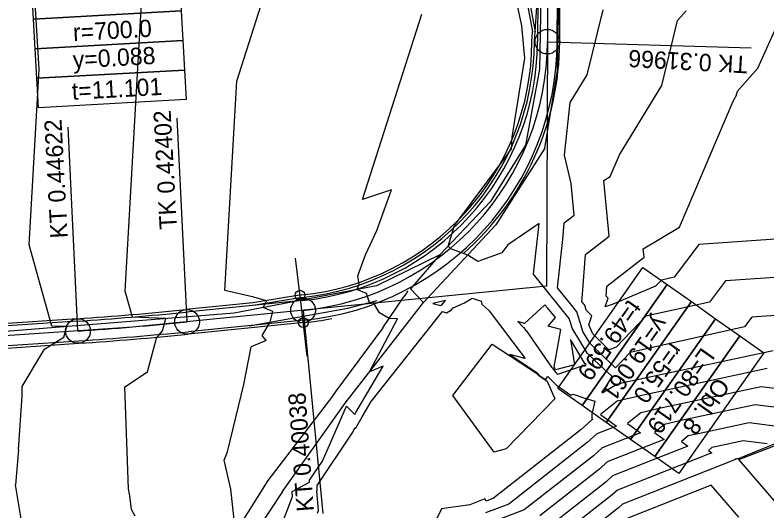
# Model space of a CAD drawing. Extents: x -549394 to -546608, y -1037055 to -1033629.
# Drawn here: x -547750.8 to -547598.3, y -1035451.6 to -1035351 of the extents above; entities that cross this region are included whole.
import ezdxf

# ---------------------------------------------------------------- set-up
doc = ezdxf.new("R2010")
doc.units = 0
for name, color, linetype in [('hlavni_vrst', 7, 'Continuous'), ('hrana_L', 7, 'Continuous'), ('norm_vrst', 7, 'Continuous'), ('POLYGONY_SITUACE_PO', 7, 'Continuous'), ('u_sirka_1_0m', 7, 'Continuous'), ('x_navrh_C1', 7, 'Continuous'), ('x_osa_C1', 7, 'Continuous'), ('x_popis_oblouky_C1', 7, 'Continuous'), ('x_popis_pricne_rezy_C1', 7, 'Continuous')]:
    doc.layers.add(name, color=color, linetype=linetype)

msp = doc.modelspace()

# ---------------------------------------------------------------- linework, layer by layer
at = {"layer": 'hlavni_vrst'}
for p, q in [((-547647.98, -1035353.14), (-547650.68, -1035340.75)), ((-547647.39, -1035359.7), (-547647.98, -1035353.14)), ((-547649.93, -1035375.76), (-547647.39, -1035359.7)), ((-547650.08, -1035378.1), (-547649.93, -1035375.76)), ((-547651.52, -1035380.05), (-547650.08, -1035378.1)), ((-547661.62, -1035393.67), (-547651.52, -1035380.05)), ((-547662.95, -1035397.82), (-547661.62, -1035393.67)), ((-547644.51, -1035393.23), (-547650.83, -1035397.56)), ((-547645.62, -1035403.52), (-547644.51, -1035393.23)), ((-547650.83, -1035397.56), (-547652.05, -1035399.2)), ((-547662.37, -1035398.39), (-547662.95, -1035397.82)), ((-547658.97, -1035399.67), (-547662.37, -1035398.39)), ((-547656.9, -1035400.98), (-547658.97, -1035399.67)), ((-547652.05, -1035399.2), (-547656.9, -1035400.98)), ((-547640.35, -1035410.1), (-547645.62, -1035403.52)), ((-547661.95, -1035410.34), (-547659.65, -1035409.33)), ((-547659.65, -1035409.33), (-547658.1, -1035408.42)), ((-547658.1, -1035408.42), (-547656.27, -1035409.01)), ((-547656.27, -1035409.01), (-547656.09, -1035409.61)), ((-547656.09, -1035409.61), (-547654.6, -1035410.95)), ((-547678.52, -1035429.33), (-547664.06, -1035411.12)), ((-547664.06, -1035411.12), (-547663.26, -1035411.34)), ((-547663.26, -1035411.34), (-547662.29, -1035410.73)), ((-547662.29, -1035410.73), (-547661.95, -1035410.34)), ((-547654.6, -1035410.95), (-547647.35, -1035420.64)), ((-547638.38, -1035412.49), (-547640.35, -1035410.1)), ((-547638.06, -1035413.56), (-547638.38, -1035412.49)), ((-547637.78, -1035414.45), (-547638.06, -1035413.56)), ((-547634.65, -1035419.6), (-547637.78, -1035414.45)), ((-547647.35, -1035420.64), (-547650.46, -1035419.84)), ((-547650.46, -1035419.84), (-547644.86, -1035423.52)), ((-547633.26, -1035420.98), (-547634.65, -1035419.6)), ((-547596.99, -1035419.04), (-547627.42, -1035425.56)), ((-547629.69, -1035424.3), (-547633.26, -1035420.98)), ((-547644.33, -1035424.14), (-547644.86, -1035423.52)), ((-547644.33, -1035424.14), (-547643.18, -1035424.92)), ((-547643.18, -1035424.92), (-547642.7, -1035424.3)), ((-547642.7, -1035424.3), (-547640.93, -1035426.07)), ((-547631.68, -1035427.63), (-547629.69, -1035424.3)), ((-547640.93, -1035426.07), (-547638.06, -1035428.05)), ((-547628.73, -1035425.87), (-547631.68, -1035427.63)), ((-547627.42, -1035425.56), (-547628.73, -1035425.87)), ((-547638.06, -1035428.05), (-547637.58, -1035427.89)), ((-547637.58, -1035427.89), (-547635.4, -1035428.6)), ((-547680.35, -1035432.43), (-547678.52, -1035429.33)), ((-547635.4, -1035428.6), (-547633.2, -1035429.31)), ((-547633.2, -1035429.31), (-547633.77, -1035431.89)), ((-547681.72, -1035434.81), (-547680.35, -1035432.43)), ((-547633.77, -1035431.89), (-547633.81, -1035432.76)), ((-547633.81, -1035433.08), (-547635.99, -1035435.06)), ((-547633.81, -1035432.76), (-547633.8, -1035432.83)), ((-547633.58, -1035432.99), (-547633.81, -1035433.08)), ((-547633.8, -1035432.83), (-547633.58, -1035432.99)), ((-547689.5, -1035446.37), (-547682.27, -1035435.59)), ((-547682.27, -1035435.59), (-547681.86, -1035434.67)), ((-547681.86, -1035434.67), (-547681.72, -1035434.81)), ((-547635.99, -1035435.06), (-547653.72, -1035448.96)), ((-547609.45, -1035438.69), (-547610.16, -1035439.26)), ((-547608.41, -1035438.45), (-547609.45, -1035438.69)), ((-547603.13, -1035437.32), (-547608.41, -1035438.45)), ((-547598.25, -1035437.97), (-547603.13, -1035437.32)), ((-547609.48, -1035439.74), (-547628.59, -1035447.31)), ((-547610.16, -1035439.26), (-547609.48, -1035439.74)), ((-547689.51, -1035447.51), (-547689.5, -1035446.37)), ((-547689.58, -1035447.55), (-547689.51, -1035447.51)), ((-547689.22, -1035451.44), (-547689.58, -1035447.55)), ((-547628.59, -1035447.31), (-547629.64, -1035448.26)), ((-547655.48, -1035449.1), (-547658.55, -1035450.34)), ((-547655.24, -1035449.54), (-547655.48, -1035449.1)), ((-547653.72, -1035448.96), (-547655.24, -1035449.54)), ((-547629.64, -1035448.26), (-547638.14, -1035454.93)), ((-547658.55, -1035450.34), (-547664.28, -1035451.11)), ((-547689.44, -1035452.02), (-547689.22, -1035451.44)), ((-547664.28, -1035451.11), (-547670.13, -1035463.03))]:
    msp.add_line(p, q, dxfattribs=at)
at = {"layer": 'hrana_L'}
for p, q in [((-547643.97, -1035335.51), (-547644.38, -1035361.94)), ((-547640.75, -1035362.22), (-547640.27, -1035335.27)), ((-547644.38, -1035361.94), (-547647.23, -1035377.35)), ((-547643.35, -1035377.93), (-547640.75, -1035362.22)), ((-547647.23, -1035377.35), (-547654.32, -1035388.75)), ((-547643.35, -1035377.93), (-547653.27, -1035393.54)), ((-547654.32, -1035388.75), (-547664.64, -1035399.6)), ((-547667.91, -1035409.29), (-547653.27, -1035393.54)), ((-547664.64, -1035399.6), (-547677.46, -1035405.86)), ((-547664.64, -1035399.6), (-547670.59, -1035406.48)), ((-547677.46, -1035405.86), (-547706.33, -1035411.42)), ((-547667.91, -1035409.29), (-547670.59, -1035406.48)), ((-547676.17, -1035414.41), (-547671.94, -1035408.13)), ((-547671.28, -1035407.14), (-547671.94, -1035408.13)), ((-547671.28, -1035407.14), (-547671.11, -1035406.86)), ((-547683.81, -1035429.72), (-547667.91, -1035409.29)), ((-547683.3, -1035410.4), (-547677.37, -1035408.87)), ((-547703.28, -1035414.02), (-547683.3, -1035410.4)), ((-547706.33, -1035411.42), (-547756.77, -1035415.5)), ((-547676.17, -1035414.41), (-547685.69, -1035427.24)), ((-547685.69, -1035427.24), (-547686.59, -1035428.55)), ((-547686.59, -1035428.55), (-547699.54, -1035445.41)), ((-547696.51, -1035447.59), (-547683.81, -1035429.72)), ((-547699.54, -1035445.41), (-547712.17, -1035465.45)), ((-547696.51, -1035447.59), (-547709.78, -1035467.43))]:
    msp.add_line(p, q, dxfattribs=at)
at = {"layer": 'norm_vrst'}
for p, q in [((-547728.43, -1035406.99), (-547724.59, -1035338.68)), ((-547705.79, -1035364.36), (-547697.76, -1035339.16)), ((-547600.1, -1035361.72), (-547589.66, -1035338.3)), ((-547745.88, -1035361.93), (-547747.23, -1035340.5)), ((-547634.71, -1035363.08), (-547631.51, -1035349.89)), ((-547616.41, -1035352.04), (-547614.65, -1035350.07)), ((-547680.29, -1035388.4), (-547668.31, -1035350.8)), ((-547619.6, -1035365.22), (-547616.41, -1035352.04)), ((-547747.89, -1035397.56), (-547745.88, -1035361.93)), ((-547604.26, -1035366.39), (-547600.1, -1035361.72)), ((-547600.1, -1035361.72), (-547600.1, -1035361.72)), ((-547600.1, -1035361.72), (-547600.1, -1035361.72)), ((-547600.1, -1035361.72), (-547600.1, -1035361.72)), ((-547600.1, -1035361.72), (-547600.1, -1035361.72)), ((-547600.1, -1035361.72), (-547600.1, -1035361.72)), ((-547638.16, -1035368.73), (-547634.71, -1035363.08)), ((-547708.21, -1035406.83), (-547705.79, -1035364.36)), ((-547628.21, -1035379.29), (-547619.6, -1035365.22)), ((-547604.5, -1035367.37), (-547604.26, -1035366.39)), ((-547616, -1035394), (-547605.14, -1035368.41)), ((-547605.14, -1035368.41), (-547604.5, -1035367.37)), ((-547639.31, -1035379.36), (-547638.16, -1035368.73)), ((-547630.09, -1035383.74), (-547628.21, -1035379.29)), ((-547638.01, -1035385.14), (-547639.31, -1035379.36)), ((-547631.37, -1035384.49), (-547630.09, -1035383.74)), ((-547637.41, -1035391.55), (-547638.01, -1035385.14)), ((-547630.31, -1035395.83), (-547631.37, -1035384.49)), ((-547674.41, -1035386.43), (-547680.29, -1035388.4)), ((-547677.41, -1035394.64), (-547674.41, -1035386.43)), ((-547639.43, -1035393.12), (-547637.41, -1035391.55)), ((-547639.68, -1035396.51), (-547639.43, -1035393.12)), ((-547623.36, -1035398.37), (-547616, -1035394)), ((-547679.71, -1035399.6), (-547677.41, -1035394.64)), ((-547635.08, -1035399.54), (-547630.31, -1035395.83)), ((-547584.5, -1035395.56), (-547612.1, -1035397.52)), ((-547743.35, -1035414.04), (-547747.89, -1035397.56)), ((-547640.73, -1035406.29), (-547639.68, -1035396.51)), ((-547612.1, -1035397.52), (-547617.09, -1035404.15)), ((-547623.2, -1035400.1), (-547623.36, -1035398.37)), ((-547681.26, -1035403.85), (-547679.71, -1035399.6)), ((-547635.68, -1035407.58), (-547635.08, -1035399.54)), ((-547630.73, -1035405.96), (-547623.2, -1035400.1)), ((-547588.83, -1035403.62), (-547606.71, -1035404.89)), ((-547681, -1035405.64), (-547681.26, -1035403.85)), ((-547619.67, -1035404.73), (-547620.87, -1035405.97)), ((-547617.09, -1035404.15), (-547619.67, -1035404.73)), ((-547606.71, -1035404.89), (-547609.94, -1035409.18)), ((-547681.45, -1035406.63), (-547681, -1035405.64)), ((-547679.47, -1035407.42), (-547681.45, -1035406.63)), ((-547637.88, -1035409.86), (-547640.73, -1035406.29)), ((-547630.88, -1035407.97), (-547630.73, -1035405.96)), ((-547620.87, -1035405.97), (-547629.7, -1035409.66)), ((-547726.98, -1035412.27), (-547728.43, -1035406.99)), ((-547702.32, -1035408.17), (-547708.21, -1035406.83)), ((-547699.81, -1035408.9), (-547702.32, -1035408.17)), ((-547678.91, -1035409.27), (-547679.47, -1035407.42)), ((-547635.84, -1035409.07), (-547635.68, -1035407.58)), ((-547630.48, -1035408.36), (-547630.88, -1035407.97)), ((-547700.44, -1035410.29), (-547699.81, -1035408.9)), ((-547678.08, -1035409.33), (-547678.91, -1035409.27)), ((-547676.83, -1035411.37), (-547678.08, -1035409.33)), ((-547663.47, -1035408.86), (-547666.04, -1035409.45)), ((-547666.04, -1035409.45), (-547664.46, -1035409.89)), ((-547664.46, -1035409.89), (-547664.28, -1035409.78)), ((-547664.28, -1035409.78), (-547663.47, -1035408.86)), ((-547643.37, -1035409.82), (-547647.45, -1035413.53)), ((-547643.3, -1035409.74), (-547643.37, -1035409.82)), ((-547642.82, -1035410.34), (-547643.3, -1035409.74)), ((-547635.4, -1035409.61), (-547635.84, -1035409.07)), ((-547635.24, -1035409.81), (-547635.4, -1035409.61)), ((-547634.94, -1035410.81), (-547635.24, -1035409.81)), ((-547631.12, -1035410.18), (-547630.48, -1035408.36)), ((-547629.7, -1035409.66), (-547631.12, -1035410.18)), ((-547609.94, -1035409.18), (-547622.83, -1035412.07)), ((-547698.48, -1035411.07), (-547700.44, -1035410.29)), ((-547699.07, -1035413.26), (-547698.48, -1035411.07)), ((-547641.19, -1035412.32), (-547642.82, -1035410.34)), ((-547636.81, -1035411.15), (-547637.88, -1035409.86)), ((-547636.15, -1035413.32), (-547636.81, -1035411.15)), ((-547633.78, -1035411.94), (-547634.94, -1035410.81)), ((-547720.2, -1035412.54), (-547726.98, -1035412.27)), ((-547720.88, -1035414.99), (-547720.2, -1035412.54)), ((-547678.86, -1035423.36), (-547673.24, -1035412.6)), ((-547674.91, -1035412.54), (-547676.83, -1035411.37)), ((-547673.24, -1035412.6), (-547674.91, -1035412.54)), ((-547642.66, -1035414.07), (-547641.19, -1035412.32)), ((-547634.43, -1035413.79), (-547633.78, -1035411.94)), ((-547622.83, -1035412.07), (-547628.84, -1035418.3)), ((-547601.32, -1035412.26), (-547602.8, -1035414.22)), ((-547593.16, -1035411.68), (-547601.32, -1035412.26)), ((-547740.29, -1035414.17), (-547743.35, -1035414.04)), ((-547740.9, -1035416.33), (-547740.29, -1035414.17)), ((-547700.67, -1035415.98), (-547699.07, -1035413.26)), ((-547647.45, -1035413.53), (-547648.81, -1035413.09)), ((-547648.81, -1035413.09), (-547647.69, -1035414.3)), ((-547647.69, -1035414.3), (-547647.62, -1035414.37)), ((-547647.62, -1035414.37), (-547647.15, -1035415)), ((-547640.08, -1035414.77), (-547642.66, -1035414.07)), ((-547635.59, -1035415.14), (-547636.15, -1035413.32)), ((-547633.62, -1035415.62), (-547634.43, -1035413.79)), ((-547602.8, -1035414.22), (-547626, -1035419.41)), ((-547722.1, -1035416.53), (-547720.88, -1035414.99)), ((-547647.15, -1035415), (-547647.11, -1035414.95)), ((-547647.11, -1035414.95), (-547641.97, -1035422.4)), ((-547641.45, -1035422.31), (-547640.08, -1035414.77)), ((-547634.11, -1035417.57), (-547635.59, -1035415.14)), ((-547630.34, -1035418.89), (-547633.62, -1035415.62)), ((-547744.84, -1035418.71), (-547740.9, -1035416.33)), ((-547723.93, -1035423.33), (-547722.1, -1035416.53)), ((-547699.86, -1035417), (-547702.88, -1035418.25)), ((-547699.86, -1035417), (-547700.67, -1035415.98)), ((-547635.19, -1035421.62), (-547638.15, -1035416.76)), ((-547638.15, -1035416.76), (-547637.29, -1035421.92)), ((-547745.43, -1035419.76), (-547744.84, -1035418.71)), ((-547704.41, -1035425.92), (-547702.88, -1035418.25)), ((-547662, -1035428.11), (-547654.04, -1035417.7)), ((-547654.04, -1035417.7), (-547644.84, -1035423.75)), ((-547631.38, -1035420.28), (-547634.11, -1035417.57)), ((-547629.72, -1035418.67), (-547630.34, -1035418.89)), ((-547628.84, -1035418.3), (-547629.72, -1035418.67)), ((-547749.31, -1035426.34), (-547745.43, -1035419.76)), ((-547628.99, -1035422.51), (-547631.38, -1035420.28)), ((-547626, -1035419.41), (-547628.99, -1035422.51)), ((-547637.29, -1035421.92), (-547641.14, -1035422.95)), ((-547640.69, -1035423.79), (-547635.33, -1035422.01)), ((-547635.33, -1035422.01), (-547635.1, -1035422.09)), ((-547635.13, -1035421.68), (-547635.19, -1035421.62)), ((-547634.96, -1035421.84), (-547635.13, -1035421.68)), ((-547635.1, -1035422.09), (-547634.96, -1035421.84)), ((-547728.53, -1035426.36), (-547723.93, -1035423.33)), ((-547681.63, -1035431.55), (-547676.1, -1035422.19)), ((-547676.1, -1035422.19), (-547678.86, -1035423.36)), ((-547641.97, -1035422.4), (-547641.87, -1035422.51)), ((-547641.87, -1035422.51), (-547641.1, -1035423.44)), ((-547641.14, -1035422.95), (-547641.45, -1035422.31)), ((-547641.1, -1035423.44), (-547640.9, -1035423.64)), ((-547598.22, -1035422.69), (-547623.62, -1035428.14)), ((-547644.6, -1035424.03), (-547644.84, -1035423.75)), ((-547644.6, -1035424.03), (-547642.88, -1035425.2)), ((-547640.9, -1035423.64), (-547640.69, -1035423.79)), ((-547749.32, -1035428.27), (-547749.31, -1035426.34)), ((-547727.79, -1035447.08), (-547728.53, -1035426.36)), ((-547707.69, -1035439.57), (-547704.41, -1035425.92)), ((-547642.88, -1035425.2), (-547641.29, -1035428.81)), ((-547599.44, -1035426.35), (-547619.82, -1035430.72)), ((-547567.08, -1035425.79), (-547604.13, -1035441.01)), ((-547603.97, -1035441.1), (-547566.27, -1035426.59)), ((-547580.62, -1035428.85), (-547599.44, -1035426.35)), ((-547653.59, -1035439.61), (-547662, -1035428.11)), ((-547750.1, -1035439.07), (-547749.32, -1035428.27)), ((-547641.29, -1035428.81), (-547651.17, -1035438.94)), ((-547628.63, -1035429.3), (-547632.01, -1035432)), ((-547623.62, -1035428.14), (-547628.63, -1035429.3)), ((-547688.45, -1035441.45), (-547683.57, -1035430.33)), ((-547683.57, -1035430.33), (-547681.88, -1035431.97)), ((-547619.82, -1035430.72), (-547623.84, -1035431.65)), ((-547600.67, -1035430.01), (-547616.01, -1035433.3)), ((-547586.5, -1035431.89), (-547600.67, -1035430.01)), ((-547681.88, -1035431.97), (-547681.63, -1035431.55)), ((-547632.01, -1035432), (-547628.76, -1035434.34)), ((-547623.84, -1035431.65), (-547626.55, -1035433.82)), ((-547626.55, -1035433.82), (-547623.94, -1035435.69)), ((-547619.04, -1035434), (-547621.08, -1035435.63)), ((-547616.01, -1035433.3), (-547619.04, -1035434)), ((-547601.9, -1035433.66), (-547612.21, -1035435.88)), ((-547592.37, -1035434.93), (-547601.9, -1035433.66)), ((-547628.76, -1035434.34), (-547632.76, -1035435.93)), ((-547623.94, -1035435.69), (-547631.72, -1035438.77)), ((-547621.08, -1035435.63), (-547619.12, -1035437.04)), ((-547632.76, -1035435.93), (-547634.72, -1035437.7)), ((-547619.12, -1035437.04), (-547630.68, -1035441.62)), ((-547614.25, -1035436.34), (-547615.62, -1035437.44)), ((-547612.21, -1035435.88), (-547614.25, -1035436.34)), ((-547634.72, -1035437.7), (-547650.6, -1035450.15)), ((-547631.72, -1035438.77), (-547633.45, -1035440.34)), ((-547614.3, -1035438.39), (-547629.63, -1035444.46)), ((-547615.62, -1035437.44), (-547614.3, -1035438.39)), ((-547750.1, -1035439.07), (-547750.68, -1035446.26)), ((-547708.34, -1035441.22), (-547707.69, -1035439.57)), ((-547651.17, -1035438.94), (-547653.59, -1035439.61)), ((-547707.04, -1035447.13), (-547708.34, -1035441.22)), ((-547691.05, -1035445.33), (-547688.45, -1035441.45)), ((-547633.45, -1035440.34), (-547647.49, -1035451.35)), ((-547630.68, -1035441.62), (-547632.18, -1035442.98)), ((-547604.66, -1035441.09), (-547627.55, -1035450.16)), ((-547604.66, -1035441.04), (-547604.69, -1035441.07)), ((-547604.69, -1035441.07), (-547604.66, -1035441.09)), ((-547604.61, -1035441.03), (-547604.66, -1035441.04)), ((-547604.36, -1035440.98), (-547604.61, -1035441.03)), ((-547604.13, -1035441.01), (-547604.36, -1035440.98)), ((-547596.39, -1035449.88), (-547603.97, -1035441.1)), ((-547632.18, -1035442.98), (-547644.37, -1035452.54)), ((-547629.63, -1035444.46), (-547630.91, -1035445.62)), ((-547746.24, -1035472.94), (-547750.68, -1035446.26)), ((-547694.6, -1035447.58), (-547691.06, -1035445.74)), ((-547691.06, -1035445.74), (-547691.05, -1035445.33)), ((-547630.91, -1035445.62), (-547641.26, -1035453.73)), ((-547609.59, -1035446.3), (-547626.5, -1035453)), ((-547603.97, -1035452.8), (-547609.59, -1035446.3)), ((-547727.49, -1035448.47), (-547727.79, -1035447.08)), ((-547706.2, -1035454.57), (-547707.04, -1035447.13)), ((-547694.5, -1035448.65), (-547694.6, -1035447.58)), ((-547727.17, -1035451.25), (-547727.49, -1035448.47)), ((-547698.44, -1035458.84), (-547694.5, -1035448.65)), ((-547650.6, -1035450.15), (-547655.37, -1035451.96)), ((-547628.37, -1035450.9), (-547635.03, -1035456.12)), ((-547627.55, -1035450.16), (-547628.37, -1035450.9)), ((-547726.4, -1035452.64), (-547727.17, -1035451.25)), ((-547647.49, -1035451.35), (-547655.5, -1035454.38))]:
    msp.add_line(p, q, dxfattribs=at)
at = {"layer": 'POLYGONY_SITUACE_PO'}
for centre in [(-547642.81, -1035356.36), (-547692.37, -1035410.86), (-547715.9, -1035413.2), (-547738.02, -1035415.05)]:
    msp.add_circle(centre, 2.5, dxfattribs=at)
at = {"layer": 'u_sirka_1_0m'}
for centre in [(-547692.99, -1035407.79), (-547692.32, -1035413.37)]:
    msp.add_circle(centre, 1, dxfattribs=at)
at = {"layer": 'x_navrh_C1'}
for p, q in [((-547644.65, -1035317.12), (-547644.81, -1035356.35)), ((-547640.81, -1035356.37), (-547640.65, -1035317.14)), ((-547640.31, -1035356.37), (-547640.15, -1035317.14)), ((-547647.27, -1035346.39), (-547645.81, -1035354.36)), ((-547646.77, -1035346.34), (-547645.31, -1035354.33)), ((-547645.45, -1035356.35), (-547644.77, -1035346.35)), ((-547645.95, -1035356.33), (-547645.81, -1035354.36)), ((-547692.69, -1035407.74), (-547702.58, -1035409.37)), ((-547692.63, -1035408.24), (-547702.51, -1035409.86)), ((-547702.58, -1035409.37), (-547716.15, -1035410.71)), ((-547738.19, -1035412.55), (-547791.51, -1035416.15)), ((-547738.15, -1035413.05), (-547791.47, -1035416.65)), ((-547692.12, -1035413.35), (-547715.65, -1035415.69)), ((-547791.2, -1035420.64), (-547737.88, -1035417.04)), ((-547791.17, -1035421.14), (-547737.85, -1035417.54))]:
    msp.add_line(p, q, dxfattribs=at)
for points in [[(-547692.56, -1035408.87), (-547716.1, -1035411.21)], [(-547692.17, -1035412.85), (-547715.7, -1035415.19)]]:
    msp.add_lwpolyline(points, dxfattribs=at)
for centre, radius, start, end in [((-547697.81, -1035356.13), 51.86, 275.6595, 359.7831), ((-547697.81, -1035356.13), 52.36, 275.6771, 359.7655), ((-547697.81, -1035356.13), 53, 275.6771, 359.7655), ((-547697.81, -1035356.13), 57, 275.6771, 359.7655), ((-547697.81, -1035356.13), 57.5, 311.3261, 359.7655), ((-547785.14, -1034716.64), 697.5, 273.8601, 275.67712), ((-547785.14, -1034716.64), 698, 273.8601, 275.67712), ((-547697.81, -1035356.13), 57.5, 275.6771, 281.2931), ((-547785.14, -1034716.64), 702, 273.8601, 275.67712), ((-547785.14, -1034716.64), 702.5, 273.8601, 275.67712)]:
    msp.add_arc(centre, radius, start, end, dxfattribs=at)
at = {"layer": 'x_osa_C1'}
for points in [[(-547641.69, -1035236.68), (-547642.59, -1035303.09), (-547642.59, -1035303.09), (-547643.01, -1035405.96)], [(-547643.01, -1035405.96), (-547726.94, -1035414.3), (-547809.81, -1035419.89), (-547892.71, -1035431.69)]]:
    msp.add_lwpolyline(points, dxfattribs=at)
for centre, radius, start, end in [((-547697.81, -1035356.13), 55, 275.6771, 359.7655), ((-547785.14, -1034716.64), 700, 273.8601, 275.67712)]:
    msp.add_arc(centre, radius, start, end, dxfattribs=at)
at = {"layer": 'x_popis_oblouky_C1'}
for points in [[(-547747.36, -1035345.79), (-547717.41, -1035344.14), (-547717.08, -1035350.13), (-547747.03, -1035351.79)], [(-547747.03, -1035351.79), (-547717.08, -1035350.13), (-547716.75, -1035356.12), (-547746.7, -1035357.78)], [(-547746.7, -1035357.78), (-547716.75, -1035356.12), (-547716.41, -1035362.11), (-547746.37, -1035363.77)], [(-547746.37, -1035363.77), (-547716.41, -1035362.11), (-547716.08, -1035368.1), (-547746.04, -1035369.76)], [(-547618.52, -1035405.64), (-547635.78, -1035430.18), (-547640.69, -1035426.73), (-547623.43, -1035402.19)], [(-547613.61, -1035409.09), (-547630.87, -1035433.64), (-547635.78, -1035430.18), (-547618.52, -1035405.64)], [(-547608.71, -1035412.55), (-547625.96, -1035437.09), (-547630.87, -1035433.64), (-547613.61, -1035409.09)], [(-547603.8, -1035416), (-547621.05, -1035440.54), (-547625.96, -1035437.09), (-547608.71, -1035412.55)], [(-547598.89, -1035419.45), (-547616.15, -1035443.99), (-547621.05, -1035440.54), (-547603.8, -1035416)]]:
    msp.add_lwpolyline(points, close=True, dxfattribs=at)
for points in [[(-547642.81, -1035356.36), (-547601.45, -1035357.59)], [(-547715.9, -1035413.2), (-547717.87, -1035371.88)], [(-547738.02, -1035415.05), (-547740.02, -1035373.72)], [(-547692.37, -1035410.86), (-547688.36, -1035452.04)]]:
    msp.add_lwpolyline(points, dxfattribs=at)
at = {"layer": 'x_popis_pricne_rezy_C1'}
msp.add_lwpolyline([(-547691.51, -1035420.13), (-547692.7, -1035410.2), (-547693.89, -1035400.27)], dxfattribs=at)

# ---------------------------------------------------------------- texts
at = {"layer": 'x_popis_oblouky_C1'}
for s, rotation, p in [('r=700.0', 3.1882, (-547738.94, -1035356.23)), ('y=0.088', 3.1882, (-547738.98, -1035361.8)), ('TK 0.31966', 176.9234, (-547602.12, -1035359.3)), ('t=11.101', 3.1882, (-547739.17, -1035368.17)), ('TK 0.42402', 93.0355, (-547717.95, -1035394.35)), ('KT 0.44622', 93.0781, (-547740.08, -1035396.16)), ('t=49.599', 234.9084, (-547626.35, -1035408.44)), ('y=19.061', 234.9084, (-547620.88, -1035411.71)), ('r=55.0', 234.9084, (-547617.88, -1035417.1)), ('L=80.719', 234.9084, (-547611.5, -1035418.17)), ('Obl. 8', 234.9084, (-547608.44, -1035424.24)), ('KT 0.40038', 94.1788, (-547690.15, -1035451.56))]:
    msp.add_text(s, height=3.5, rotation=rotation, dxfattribs=at).set_placement(p)

doc.saveas('drawing.dxf')
